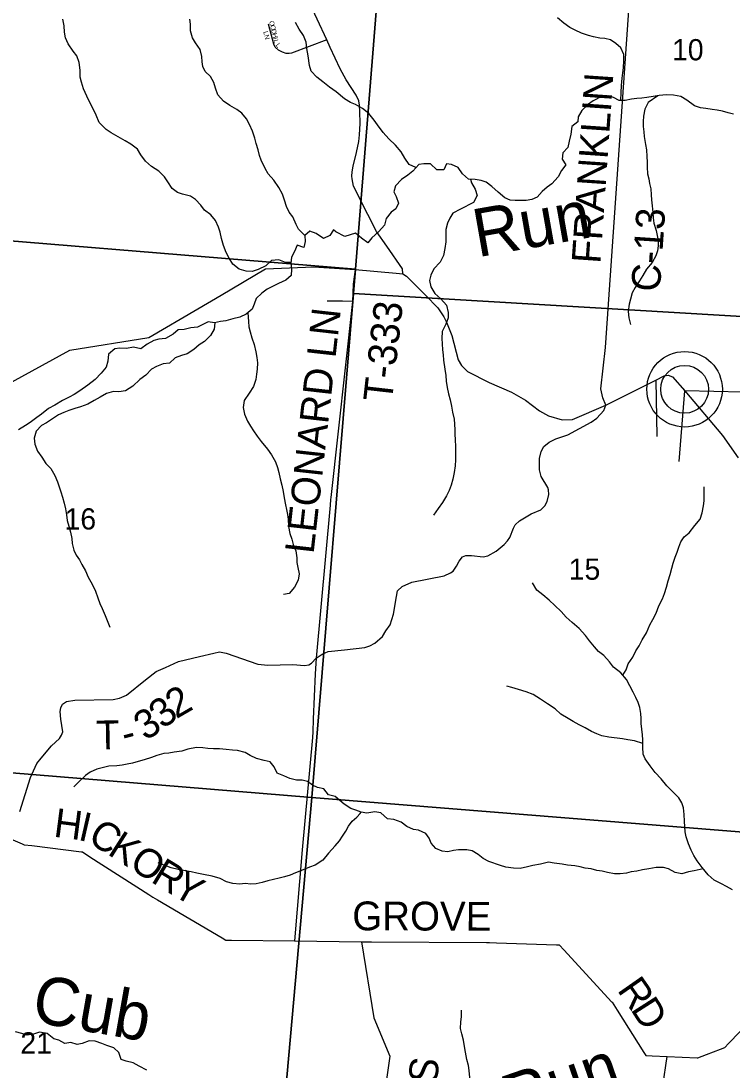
# Model space of a CAD drawing. Extents: x 1715311 to 2083412, y 146837 to 553079.
# Drawn here: x 1929652 to 1937058, y 321945 to 332866 of the extents above; entities that cross this region are included whole.
import ezdxf

# ---------------------------------------------------------------- set-up
doc = ezdxf.new("R2010")
doc.units = 0
for name, color, linetype in [('GM_X_County_Road', 7, 'Continuous'), ('GM_X_County_Road_Text', 7, 'Continuous'), ('GM_X_Minor_River', 7, 'Continuous'), ('GM_X_Minor_River_Text', 7, 'Continuous'), ('GM_X_Section', 7, 'Continuous'), ('GM_X_Section_Text', 7, 'Continuous'), ('GM_X_State_Route', 7, 'Continuous'), ('GM_X_Township_Road', 7, 'Continuous'), ('GM_X_Township_Road_Text', 7, 'Continuous'), ('GM_X_Township_ROW', 7, 'Continuous'), ('GM_X_Township_Subdivision', 7, 'Continuous'), ('GM_X_Township_Subdivision_Text', 7, 'Continuous'), ('GM_X_Unincorporated', 7, 'Continuous'), ('GM_X_Unincorporated_Location', 7, 'Continuous')]:
    doc.layers.add(name, color=color, linetype=linetype)

msp = doc.modelspace()

# ---------------------------------------------------------------- linework, layer by layer
at = {"layer": 'GM_X_County_Road'}
for points in [[(1935743, 328867), (1935711, 328943), (1935691, 329038), (1935741, 329467), (1936012, 333380)], [(1933628, 330233), (1933626, 330286), (1933462, 330523), (1933356, 330674), (1933265, 330852), (1933117, 331145), (1933101, 331221), (1933099, 331251), (1933102, 331297), (1933113, 331355), (1933145, 331498), (1933170, 331610), (1933179, 331681), (1933186, 331798), (1933183, 331925), (1933179, 331989), (1933172, 332033), (1933142, 332094), (1933040, 332252), (1932976, 332366), (1932874, 332591), (1932838, 332669), (1932638, 333104)], [(1939690, 329520), (1939226, 329219), (1939221, 329216), (1939122, 329218), (1938495, 329231), (1938482, 329232), (1938403, 329277), (1938267, 329355), (1938242, 329370), (1938167, 329362), (1937959, 329342), (1937942, 329340), (1937878, 329280), (1937575, 328993), (1937573, 328991), (1937471, 328994), (1936565, 329016)], [(1929568, 324342), (1929663, 324301), (1929684, 324291), (1929765, 324281), (1930282, 324217), (1930294, 324215), (1930371, 324166), (1930985, 323772), (1931026, 323746), (1931074, 323718), (1931747, 323321), (1931786, 323298), (1931845, 323298), (1932501, 323289), (1933200, 323279), (1933242, 323278), (1933304, 323278), (1934502, 323272), (1934531, 323272), (1934606, 323270), (1935231, 323249), (1935259, 323248), (1935310, 323192), (1935804, 322656), (1935809, 322650), (1935861, 322568), (1936140, 322128), (1936161, 322095), (1936225, 322092), (1936381, 322086), (1936694, 322073), (1936695, 322073)], [(1936695, 322073), (1936701, 322073), (1936791, 322107), (1936937, 322163), (1936983, 322181), (1937021, 322221), (1937711, 322931), (1937748, 322969)]]:
    msp.add_lwpolyline(points, dxfattribs=at)
at = {"layer": 'GM_X_Minor_River'}
for points in [[(1932463, 330352), (1932406, 330350), (1932339, 330378), (1932263, 330374), (1932201, 330317), (1932124, 330279), (1932061, 330259), (1931997, 330263), (1931923, 330282), (1931859, 330334), (1931821, 330396), (1931790, 330454), (1931762, 330528), (1931742, 330601), (1931728, 330669), (1931709, 330721), (1931679, 330789), (1931629, 330849), (1931564, 330897), (1931526, 330948), (1931470, 331006), (1931418, 331042), (1931336, 331062), (1931281, 331081), (1931227, 331121), (1931181, 331191), (1931147, 331245), (1931088, 331304), (1931012, 331350), (1930948, 331406), (1930900, 331474), (1930867, 331531), (1930797, 331585), (1930737, 331617), (1930665, 331659), (1930592, 331700), (1930538, 331736), (1930466, 331808), (1930435, 331886), (1930411, 331937), (1930373, 332011), (1930337, 332083), (1930304, 332159), (1930284, 332229), (1930270, 332281), (1930267, 332353), (1930259, 332432), (1930233, 332502), (1930195, 332552), (1930144, 332628), (1930116, 332692), (1930104, 332748), (1930102, 332816), (1930087, 332886)], [(1932607, 330633), (1932544, 330698), (1932518, 330748), (1932482, 330826), (1932444, 330876), (1932419, 330934), (1932397, 331002), (1932377, 331064), (1932337, 331133), (1932284, 331209), (1932228, 331275), (1932194, 331329), (1932153, 331416), (1932137, 331466), (1932123, 331524), (1932101, 331592), (1932088, 331646), (1932062, 331718), (1932032, 331788), (1932002, 331848), (1931951, 331907), (1931899, 331945), (1931829, 331987), (1931763, 332031), (1931702, 332098), (1931678, 332168), (1931660, 332224), (1931627, 332288), (1931571, 332340), (1931547, 332391), (1931541, 332441), (1931537, 332497), (1931520, 332569), (1931470, 332639), (1931438, 332691), (1931419, 332763), (1931417, 332833), (1931411, 332885)], [(1935900, 332039), (1935903, 332123), (1935907, 332193), (1935915, 332269), (1935922, 332327), (1935926, 332377), (1935930, 332453), (1935930, 332517), (1935899, 332588), (1935847, 332632), (1935793, 332670), (1935734, 332684), (1935682, 332687), (1935616, 332701), (1935564, 332713), (1935490, 332738), (1935425, 332770), (1935369, 332798), (1935307, 332842), (1935240, 332899)], [(1932935, 332129), (1932867, 332177), (1932797, 332232), (1932733, 332280), (1932675, 332342), (1932658, 332404), (1932642, 332504), (1932628, 332579), (1932623, 332645), (1932593, 332713), (1932549, 332781), (1932512, 332849)], [(1933766, 331340), (1933696, 331371), (1933649, 331439), (1933611, 331505), (1933552, 331573), (1933482, 331640), (1933424, 331704), (1933365, 331784), (1933331, 331835), (1933274, 331903), (1933208, 331953), (1933136, 331998), (1933085, 332018), (1933023, 332054), (1932935, 332129)], [(1937073, 331896), (1937017, 331908), (1936958, 331926), (1936902, 331939), (1936850, 331945), (1936786, 331955), (1936728, 331961), (1936668, 331984), (1936587, 332042), (1936525, 332080), (1936447, 332095), (1936374, 332097), (1936300, 332089), (1936236, 332080), (1936170, 332068), (1936118, 332062), (1936066, 332058), (1936012, 332051), (1935946, 332037), (1935884, 332039), (1935823, 332068), (1935767, 332086), (1935699, 332080), (1935613, 332034), (1935563, 331999), (1935495, 331935), (1935455, 331869), (1935452, 331817), (1935388, 331767), (1935378, 331687), (1935360, 331615), (1935347, 331547), (1935295, 331493), (1935289, 331427), (1935327, 331367), (1935283, 331309), (1935248, 331242), (1935182, 331170), (1935132, 331136), (1935082, 331092), (1935028, 331030), (1934974, 331009), (1934912, 330997), (1934852, 330997), (1934800, 330997), (1934748, 331002), (1934691, 331024), (1934621, 331082), (1934557, 331143), (1934496, 331189), (1934444, 331205), (1934384, 331215), (1934314, 331220), (1934251, 331274), (1934207, 331342), (1934135, 331371), (1934084, 331377), (1934057, 331317), (1933984, 331317), (1933916, 331380), (1933848, 331380), (1933796, 331372), (1933734, 331304), (1933682, 331259), (1933614, 331215), (1933552, 331149), (1933534, 331087), (1933561, 331037), (1933583, 330969), (1933557, 330911)], [(1936284, 332087), (1936186, 332016), (1936149, 331948), (1936135, 331876), (1936131, 331820), (1936133, 331766), (1936138, 331712), (1936144, 331662), (1936156, 331580), (1936166, 331526), (1936171, 331455), (1936173, 331397), (1936173, 331345), (1936178, 331275), (1936190, 331223), (1936198, 331173), (1936212, 331119), (1936217, 331055), (1936219, 331003), (1936225, 330941), (1936233, 330873), (1936236, 330817), (1936244, 330761), (1936268, 330684), (1936277, 330632), (1936289, 330580), (1936289, 330524), (1936283, 330472), (1936265, 330420), (1936226, 330352), (1936168, 330283), (1936130, 330217), (1936094, 330161), (1936050, 330093), (1936019, 330037), (1935999, 329971), (1935987, 329917), (1935977, 329841), (1935984, 329775), (1936002, 329707)], [(1934335, 331218), (1934344, 331180), (1934382, 331115), (1934403, 331049), (1934365, 330975), (1934229, 330908), (1934149, 330866), (1934117, 330814), (1934093, 330762), (1934077, 330694), (1934076, 330566), (1934066, 330496), (1934053, 330424), (1934017, 330354), (1933953, 330285), (1933921, 330219), (1933907, 330163), (1933922, 330099), (1933964, 330030), (1934024, 329974), (1934083, 329906), (1934101, 329832), (1934103, 329776), (1934076, 329708), (1934038, 329632), (1934036, 329562), (1934038, 329504), (1934043, 329442), (1934049, 329392), (1934053, 329336), (1934066, 329241), (1934076, 329175), (1934082, 329115), (1934091, 329051), (1934105, 328985), (1934121, 328923), (1934135, 328855), (1934148, 328793), (1934164, 328719), (1934166, 328667), (1934171, 328610), (1934171, 328560), (1934175, 328508), (1934177, 328432), (1934178, 328374), (1934178, 328296), (1934176, 328234), (1934163, 328166), (1934151, 328096), (1934131, 328034), (1934111, 327978), (1934085, 327924), (1934044, 327854), (1933998, 327789), (1933948, 327721)], [(1933557, 330911), (1933507, 330877), (1933456, 330809), (1933440, 330739), (1933378, 330674), (1933308, 330610), (1933264, 330558), (1933200, 330606), (1933135, 330657), (1933024, 330623), (1932933, 330672)], [(1932933, 330672), (1932907, 330690), (1932869, 330632), (1932803, 330600), (1932727, 330653), (1932661, 330677), (1932607, 330633), (1932611, 330569), (1932597, 330507), (1932527, 330532), (1932501, 330466), (1932469, 330406), (1932462, 330346), (1932470, 330282), (1932466, 330216), (1932410, 330168), (1932334, 330134), (1932280, 330106), (1932218, 330074), (1932160, 330033), (1932101, 329977), (1932081, 329919), (1932061, 329867), (1931999, 329813), (1931933, 329783), (1931857, 329764), (1931787, 329746), (1931731, 329738), (1931667, 329724), (1931603, 329734), (1931541, 329703), (1931489, 329677), (1931421, 329671), (1931353, 329655), (1931289, 329650), (1931239, 329604), (1931157, 329562), (1931087, 329554), (1931035, 329541), (1930965, 329503), (1930899, 329453), (1930825, 329469), (1930751, 329458), (1930681, 329460), (1930629, 329454), (1930565, 329398), (1930557, 329326), (1930541, 329262), (1930487, 329198), (1930424, 329135), (1930348, 329075), (1930264, 329017), (1930206, 328979), (1930154, 328949), (1930086, 328916), (1930006, 328868), (1929940, 328830), (1929866, 328772), (1929816, 328737), (1929748, 328687), (1929698, 328655), (1929626, 328611)], [(1932014, 329826), (1932023, 329739), (1932024, 329681), (1932040, 329629), (1932058, 329567), (1932080, 329498), (1932097, 329420), (1932109, 329364), (1932117, 329308), (1932111, 329242), (1932106, 329188), (1932098, 329132), (1932074, 329062), (1932028, 328992), (1931976, 328916), (1931965, 328842), (1931981, 328774), (1932013, 328700), (1932043, 328648), (1932074, 328598), (1932112, 328542), (1932154, 328489), (1932221, 328407), (1932261, 328349), (1932303, 328275), (1932325, 328219), (1932338, 328167), (1932350, 328098), (1932368, 328034), (1932382, 327968), (1932395, 327900), (1932407, 327830), (1932417, 327780), (1932427, 327728), (1932434, 327678), (1932440, 327602), (1932454, 327532), (1932472, 327470), (1932487, 327417), (1932515, 327349), (1932525, 327277), (1932525, 327227), (1932534, 327177), (1932550, 327111), (1932540, 327045), (1932500, 326973), (1932444, 326905), (1932388, 326895)], [(1931670, 329725), (1931665, 329658), (1931627, 329590), (1931562, 329528), (1931508, 329493), (1931454, 329447), (1931382, 329401), (1931324, 329385), (1931258, 329358), (1931198, 329302), (1931134, 329296), (1931064, 329268), (1931012, 329240), (1930954, 329179), (1930890, 329135), (1930816, 329063), (1930742, 329017), (1930670, 329004), (1930616, 329010), (1930544, 328988), (1930476, 328950), (1930414, 328914), (1930350, 328877), (1930272, 328849), (1930214, 328831), (1930152, 328811), (1930100, 328790), (1930044, 328764), (1929990, 328732), (1929919, 328682), (1929867, 328656), (1929809, 328595), (1929789, 328523), (1929795, 328459), (1929824, 328386), (1929868, 328326), (1929910, 328260), (1929964, 328208), (1930005, 328133), (1930031, 328067), (1930067, 327963), (1930084, 327909), (1930102, 327845), (1930116, 327787), (1930126, 327725), (1930135, 327665), (1930149, 327605), (1930169, 327544), (1930183, 327478), (1930186, 327426), (1930202, 327358), (1930226, 327306), (1930262, 327256), (1930287, 327206), (1930323, 327142), (1930351, 327075), (1930393, 327003), (1930430, 326931), (1930454, 326859), (1930472, 326801), (1930498, 326751), (1930529, 326678), (1930551, 326626), (1930579, 326556)], [(1935922, 326055), (1935955, 326112), (1935975, 326172), (1936023, 326242), (1936055, 326310), (1936089, 326362), (1936122, 326424), (1936166, 326498), (1936202, 326578), (1936232, 326634), (1936266, 326701), (1936297, 326777), (1936333, 326851), (1936353, 326905), (1936377, 326973), (1936394, 327039), (1936412, 327103), (1936430, 327169), (1936446, 327223), (1936465, 327283), (1936487, 327335), (1936503, 327387), (1936525, 327443), (1936561, 327495), (1936613, 327539), (1936670, 327614), (1936726, 327678), (1936748, 327746), (1936762, 327818), (1936768, 327872), (1936767, 327948), (1936769, 328016)], [(1937062, 323820), (1936999, 323854), (1936947, 323882), (1936871, 323923), (1936809, 323977), (1936748, 324053), (1936696, 324122), (1936661, 324178), (1936631, 324234), (1936603, 324300), (1936580, 324374), (1936570, 324424), (1936566, 324478), (1936564, 324534), (1936559, 324605), (1936553, 324673), (1936535, 324727), (1936502, 324777), (1936436, 324847), (1936378, 324902), (1936319, 324978), (1936257, 325044), (1936204, 325113), (1936154, 325183), (1936132, 325233), (1936129, 325305), (1936129, 325383), (1936127, 325433), (1936120, 325493), (1936110, 325553), (1936112, 325605), (1936108, 325655), (1936097, 325720), (1936081, 325770), (1936057, 325824), (1936029, 325880), (1935994, 325944), (1935960, 326010), (1935901, 326081), (1935825, 326139), (1935783, 326193), (1935722, 326262), (1935668, 326302), (1935624, 326352), (1935573, 326414), (1935531, 326469), (1935464, 326541), (1935394, 326605), (1935332, 326660), (1935277, 326718), (1935213, 326782), (1935155, 326835), (1935086, 326891), (1935026, 326941), (1934979, 327016)], [(1936129, 325345), (1936043, 325372), (1935971, 325384), (1935918, 325392), (1935774, 325411), (1935702, 325425), (1935650, 325445), (1935595, 325470), (1935527, 325506), (1935467, 325538), (1935403, 325573), (1935352, 325605), (1935276, 325651), (1935216, 325704), (1935137, 325758), (1935063, 325806), (1934988, 325855), (1934912, 325881), (1934834, 325907), (1934764, 325928), (1934713, 325942)], [(1932925, 324792), (1932855, 324810), (1932808, 324872), (1932740, 324887), (1932688, 324911), (1932636, 324949), (1932582, 324961), (1932522, 324964), (1932454, 324980), (1932389, 325006), (1932321, 325036), (1932289, 325101), (1932247, 325155), (1932186, 325167), (1932104, 325189), (1932040, 325220), (1931986, 325250), (1931906, 325270), (1931854, 325276), (1931788, 325283), (1931719, 325287), (1931657, 325287), (1931599, 325293), (1931545, 325300), (1931479, 325302), (1931389, 325284), (1931329, 325266), (1931247, 325253), (1931193, 325243), (1931139, 325241), (1931067, 325219), (1931011, 325198), (1930935, 325174), (1930873, 325158), (1930813, 325140), (1930759, 325130), (1930705, 325119), (1930651, 325113), (1930569, 325107), (1930511, 325095), (1930441, 325078), (1930373, 325046), (1930323, 325010), (1930263, 324952), (1930203, 324892)], [(1936758, 324040), (1936662, 324020), (1936606, 324008), (1936536, 323988), (1936464, 324003), (1936397, 324039), (1936343, 324053), (1936267, 324052), (1936193, 324040), (1936125, 324030), (1936067, 324014), (1936009, 324007), (1935957, 323993), (1935894, 323987), (1935832, 323987), (1935760, 324002), (1935704, 324014), (1935648, 324022), (1935592, 324041), (1935527, 324047), (1935475, 324059), (1935421, 324069), (1935343, 324078), (1935289, 324088), (1935206, 324100), (1935146, 324109), (1935062, 324087), (1934982, 324075), (1934928, 324062), (1934850, 324044), (1934782, 324048), (1934702, 324057), (1934645, 324073), (1934525, 324117), (1934465, 324148), (1934414, 324190), (1934352, 324228), (1934296, 324237), (1934210, 324239), (1934158, 324231), (1934098, 324215), (1934039, 324222), (1933973, 324252), (1933925, 324306), (1933904, 324358), (1933868, 324409), (1933792, 324443), (1933740, 324449), (1933671, 324480), (1933611, 324526), (1933537, 324554), (1933471, 324559), (1933400, 324623), (1933336, 324633), (1933256, 324620), (1933194, 324630), (1933140, 324650), (1933087, 324668), (1933017, 324711), (1932925, 324792)], [(1932924, 324280), (1932970, 324330), (1933001, 324380), (1933034, 324432), (1933062, 324482), (1933100, 324536), (1933150, 324579), (1933186, 324614), (1933194, 324630)], [(1932924, 324280), (1932855, 324204), (1932795, 324130), (1932715, 324078), (1932657, 324058), (1932575, 324021), (1932513, 323997), (1932455, 323973), (1932397, 323955), (1932343, 323944), (1932283, 323930), (1932223, 323914), (1932163, 323896), (1932101, 323882), (1932047, 323879), (1931987, 323887), (1931933, 323881), (1931857, 323887), (1931793, 323904), (1931726, 323938), (1931642, 323964), (1931554, 323981), (1931484, 323993), (1931426, 324007), (1931346, 324023), (1931288, 324034), (1931215, 324050), (1931145, 324078), (1931081, 324102)], [(1934668, 321130), (1934614, 321239), (1934579, 321291), (1934543, 321347), (1934515, 321397), (1934488, 321452), (1934458, 321510), (1934426, 321588), (1934403, 321640), (1934379, 321690), (1934361, 321748), (1934345, 321799), (1934328, 321867), (1934320, 321939), (1934312, 321991), (1934295, 322055), (1934283, 322131), (1934271, 322191), (1934260, 322257), (1934242, 322323), (1934230, 322378), (1934235, 322446), (1934241, 322498), (1934241, 322568)], [(1930963, 321943), (1930883, 321984), (1930822, 322020), (1930748, 322038), (1930696, 322055), (1930670, 322127), (1930618, 322175), (1930547, 322199), (1930495, 322221), (1930425, 322244), (1930361, 322248), (1930291, 322220), (1930239, 322212), (1930173, 322233), (1930109, 322221), (1930045, 322255), (1929994, 322271), (1929926, 322324), (1929844, 322338), (1929784, 322320), (1929716, 322308), (1929662, 322325), (1929594, 322343)]]:
    msp.add_lwpolyline(points, dxfattribs=at)
at = {"layer": 'GM_X_Section'}
for points in [[(1928365, 336024), (1933565, 335605), (1933136, 330282), (1927886, 330712)], [(1933565, 335605), (1938923, 335133), (1938390, 329715), (1933115, 330029), (1933136, 330282)], [(1933136, 330282), (1933115, 330029), (1932682, 324783), (1927402, 325216), (1927886, 330712)], [(1938390, 329715), (1937908, 324363), (1932682, 324783), (1933115, 330029)], [(1927402, 325216), (1932682, 324783), (1932199, 319380), (1926983, 319817)], [(1932682, 324783), (1937908, 324363), (1937492, 318936), (1932199, 319380)]]:
    msp.add_lwpolyline(points, close=True, dxfattribs=at)
at = {"layer": 'GM_X_State_Route'}
for points in [[(1931737, 330012), (1932200, 330285), (1932700, 330306), (1933134, 330278), (1933560, 330241), (1933628, 330233)], [(1933628, 330233), (1933669, 330209), (1933865, 330010), (1933993, 329879), (1934057, 329787), (1934085, 329730), (1934139, 329593), (1934207, 329337), (1934240, 329280), (1934303, 329218), (1934527, 329102), (1934762, 329001), (1934907, 328918), (1935054, 328809), (1935146, 328755), (1935290, 328712), (1935398, 328716), (1935743, 328867), (1936265, 329127), (1936352, 329171), (1936392, 329178), (1936438, 329162), (1936565, 329016), (1936960, 328552), (1937122, 328319)], [(1922037, 321892), (1922022, 322822), (1922139, 323290), (1922626, 324122), (1922831, 324421), (1923027, 324609), (1923147, 324726), (1923604, 325404), (1923752, 325524), (1924583, 325996), (1925362, 326521), (1925955, 326736), (1926394, 327036), (1926938, 327472), (1927608, 327784), (1927831, 327887), (1928133, 328168), (1929404, 329023), (1929485, 329067), (1930160, 329438), (1930985, 329570), (1931495, 329870), (1931737, 330012)]]:
    msp.add_lwpolyline(points, dxfattribs=at)
at = {"layer": 'GM_X_Township_Road'}
for points in [[(1933134, 330278), (1933111, 330125), (1933105, 329947), (1932878, 327906)], [(1933105, 329947), (1933000, 329948), (1932894, 329950), (1932841, 329950)], [(1936265, 329127), (1936273, 328540)], [(1936508, 328279), (1936565, 329016)], [(1929642, 324636), (1929751, 324991), (1929781, 325060), (1929818, 325135), (1929861, 325192), (1929970, 325321), (1930052, 325395), (1930074, 325430), (1930089, 325465), (1930066, 325596), (1930059, 325676), (1930066, 325715), (1930086, 325755), (1930126, 325780), (1930213, 325795), (1930612, 325802), (1930679, 325815), (1930751, 325849), (1930950, 326008), (1931061, 326093), (1931156, 326137), (1931292, 326197), (1931513, 326249), (1931662, 326286), (1931721, 326298), (1931788, 326284), (1932118, 326169), (1932223, 326160), (1932352, 326162), (1932483, 326167), (1932605, 326155), (1932651, 326164), (1932677, 326182), (1932728, 326231), (1932788, 326274), (1932850, 326301), (1933023, 326321), (1933232, 326343), (1933287, 326361), (1933337, 326388), (1933416, 326457), (1933453, 326517), (1933498, 326579), (1933533, 326690), (1933562, 326874), (1933575, 326934), (1933624, 326978), (1933724, 327023), (1934059, 327090), (1934126, 327120), (1934153, 327137), (1934188, 327192), (1934215, 327241), (1934252, 327288), (1934287, 327301), (1934344, 327301), (1934466, 327286), (1934513, 327298), (1934602, 327346), (1934684, 327417), (1934721, 327455), (1934743, 327489), (1934781, 327586), (1934800, 327621), (1934845, 327663), (1934967, 327735), (1935068, 327777), (1935108, 327819), (1935133, 327864), (1935150, 327936), (1935148, 327986), (1935138, 328010), (1935071, 328125), (1935051, 328194), (1935051, 328311), (1935071, 328385), (1935098, 328437), (1935153, 328482), (1935222, 328517), (1935346, 328556), (1935592, 328688), (1935649, 328732), (1935721, 328812), (1935743, 328867)], [(1932728, 326231), (1932716, 326071), (1932696, 325599)], [(1933200, 323279), (1933327, 322489), (1933495, 322091), (1933425, 321601), (1933306, 321211)], [(1936336, 321779), (1936381, 322086)]]:
    msp.add_lwpolyline(points, dxfattribs=at)
at = {"layer": 'GM_X_Township_ROW'}
for points in [[(1932878, 327906), (1932876, 327883), (1932871, 327826), (1932728, 326231)], [(1932696, 325599), (1932691, 325466), (1932688, 325406), (1932581, 324237), (1932501, 323289)]]:
    msp.add_lwpolyline(points, dxfattribs=at)
at = {"layer": 'GM_X_Township_Subdivision'}
msp.add_lwpolyline([(1932838, 332669), (1932471, 332532), (1932445, 332526), (1932415, 332529), (1932375, 332541), (1932336, 332561), (1932299, 332594), (1932284, 332624), (1932229, 332834)], dxfattribs=at)
at = {"layer": 'GM_X_Unincorporated'}
for radius in [393, 249]:
    msp.add_circle((1936564, 329032), radius, dxfattribs=at)
at = {"layer": 'GM_X_Unincorporated_Location'}
msp.add_line((1936564, 329032), (1936564, 329032), dxfattribs=at)

# ---------------------------------------------------------------- texts
at = {"layer": 'GM_X_County_Road_Text'}
for s, rotation, p in [('FRANKLIN', 86.0502, (1935686, 330334)), ('C-13', 86.2322, (1936306, 330041)), ('H', 352.6251, (1929984, 324375)), ('I', 347.0978, (1930238, 324343)), ('C', 328.2069, (1930334, 324325)), ('K', 327.4567, (1930543, 324196)), ('O', 327.5319, (1930766, 324054)), ('R', 328.5775, (1930994, 323909)), ('Y', 329.9585, (1931211, 323776)), ('GROVE', 359.802, (1933102, 323400)), ('R', 304.9664, (1935855, 322778)), ('D', 302.522, (1935995, 322578))]:
    msp.add_text(s, height=300, rotation=rotation, dxfattribs=at).set_placement(p)
at = {"layer": 'GM_X_Minor_River_Text'}
for s, rotation, p in [('Run', 9.998, (1934408, 330405)), ('Cub', 349.9961, (1929749, 322452)), ('Run', 18.9991, (1934771, 321385))]:
    msp.add_text(s, height=500, rotation=rotation, dxfattribs=at).set_placement(p)
at = {"layer": 'GM_X_Section_Text'}
for s, p in [('10', (1936433, 332456)), ('16', (1930106, 327572)), ('15', (1935357, 327049)), ('21', (1929646, 322117))]:
    msp.add_text(s, height=221, rotation=0, dxfattribs=at).set_placement(p)
at = {"layer": 'GM_X_Township_Road_Text'}
for s, rotation, p in [('T-333', 83.5352, (1933514, 328890)), ('LEONARD LN', 83.6119, (1932699, 327312)), ('2', 30.1748, (1931269, 325596)), ('3', 38.4722, (1931134, 325487)), ('3', 32.3199, (1930949, 325368)), ('T', 1.1186, (1930437, 325282)), ('-', 14.6776, (1930738, 325297)), ('S', 81.6799, (1933977, 321788))]:
    msp.add_text(s, height=300, rotation=rotation, dxfattribs=at).set_placement(p)
at = {"layer": 'GM_X_Township_Subdivision_Text'}
for s, rotation, p in [('O', 283.75, (1932236, 332860)), ('LN', 284.7351, (1932175, 332753)), ('O', 283.7693, (1932247, 332817)), ('D', 283.75, (1932257, 332774)), ('H', 283.75, (1932268, 332732)), ('I', 283.7697, (1932278, 332689)), ('L', 283.7646, (1932283, 332667)), ('L', 309.1874, (1932302, 332612))]:
    msp.add_text(s, height=50, rotation=rotation, dxfattribs=at).set_placement(p)

doc.saveas('drawing.dxf')
